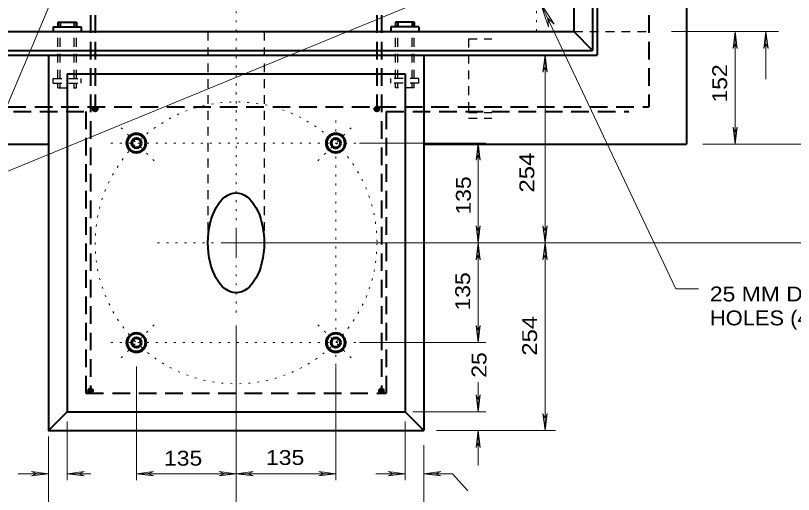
# Model space of a CAD drawing. Extents: x 312583 to 312854, y 144419 to 144597.
# Drawn here: x 312651.47 to 312691.2, y 144522.33 to 144546.77 of the extents above; entities that cross this region are included whole.
import ezdxf

# ---------------------------------------------------------------- set-up
doc = ezdxf.new("R2010")
doc.units = 0
doc.header["$LTSCALE"] = 0.3
for name, pattern in [('DOTTED', [1.5, 0.3, -1.2]), ('MEDIUM_DASHED', [4.5, 3, -1.5]), ('SHORT_DASHED', [2.7, 1.5, -1.2])]:
    doc.linetypes.add(name, pattern=pattern)
doc.layers.add('1', color=7, linetype='Continuous', lineweight=25)
doc.layers.add('2', color=7, linetype='Continuous', lineweight=13)

msp = doc.modelspace()

# ---------------------------------------------------------------- linework, layer by layer
at = {"layer": '1', "lineweight": 40}
for p, q in [((312685.7337, 144568.9533), (312685.7337, 144540.2033)), ((312679.9837, 144554.54), (312679.9837, 144545.9533)), ((312653.6257, 144546.4363), (312654.584, 144546.4363)), ((312653.6257, 144546.4363), (312653.6257, 144546.191)), ((312653.7484, 144546.4363), (312653.7484, 144546.191)), ((312654.469, 144546.4363), (312654.469, 144546.191)), ((312654.584, 144546.4363), (312654.584, 144546.191)), ((312671.834, 144546.4363), (312670.8757, 144546.4363)), ((312670.8757, 144546.4363), (312670.8757, 144546.191)), ((312670.9984, 144546.4363), (312670.9984, 144546.191)), ((312671.719, 144546.4363), (312671.719, 144546.191)), ((312671.834, 144546.4363), (312671.834, 144546.191)), ((312653.388, 144546.191), (312654.8217, 144546.191)), ((312653.388, 144546.191), (312653.388, 144545.9533)), ((312654.8217, 144546.191), (312654.8217, 144545.9533)), ((312672.0717, 144546.191), (312670.638, 144546.191)), ((312670.638, 144546.191), (312670.638, 144545.9533)), ((312672.0717, 144546.191), (312672.0717, 144545.9533)), ((312679.9837, 144545.9533), (312680.942, 144544.995)), ((312644.28, 144544.7573), (312681.1797, 144544.7573)), ((312644.5254, 144544.995), (312680.942, 144544.995)), ((312672.317, 144544.7573), (312672.317, 144525.5906)), ((312654.1087, 144543.799), (312654.1087, 144526.549)), ((312654.1087, 144543.799), (312671.3587, 144543.799)), ((312671.3587, 144543.799), (312671.3587, 144526.549)), ((312639.7337, 144540.2033), (312653.1504, 144540.2033)), ((312672.317, 144540.2033), (312685.7337, 144540.2033)), ((312654.1087, 144526.549), (312653.1504, 144525.5906)), ((312654.1087, 144526.549), (312671.3587, 144526.549)), ((312671.3587, 144526.549), (312672.317, 144525.5906))]:
    msp.add_line(p, q, dxfattribs=at)
at = {"layer": '1', "linetype": 'MEDIUM_DASHED', "lineweight": 40}
for p, q in [((312655.3047, 144567.0366), (312655.3047, 144527.6223)), ((312655.5424, 144567.0366), (312655.5424, 144542.12)), ((312669.9174, 144567.0366), (312669.9174, 144542.12)), ((312670.155, 144567.0366), (312670.155, 144527.6223)), ((312641.6504, 144542.12), (312683.817, 144542.12)), ((312643.2604, 144541.8823), (312655.067, 144541.8823)), ((312670.4004, 144541.8823), (312670.4004, 144527.5073)), ((312670.4004, 144541.8823), (312682.7974, 144541.8823))]:
    msp.add_line(p, q, dxfattribs=at)
at = {"layer": '1', "linetype": 'SHORT_DASHED'}
for p, q in [((312653.6257, 144543.5613), (312653.6257, 144545.9533)), ((312653.7484, 144543.5613), (312653.7484, 144545.9533)), ((312654.469, 144543.5613), (312654.469, 144545.9533)), ((312654.584, 144543.5613), (312654.584, 144545.9533)), ((312661.2924, 144545.9533), (312661.2924, 144535.174)), ((312664.1674, 144545.9533), (312664.1674, 144535.174)), ((312670.8757, 144543.5613), (312670.8757, 144545.9533)), ((312670.9984, 144543.5613), (312670.9984, 144545.9533)), ((312671.719, 144543.5613), (312671.719, 144545.9533)), ((312671.834, 144543.5613), (312671.834, 144545.9533)), ((312679.9837, 144545.9533), (312683.817, 144545.9533)), ((312674.594, 144545.593), (312675.79, 144545.593)), ((312674.594, 144545.593), (312674.594, 144541.5296)), ((312653.388, 144543.5613), (312654.8217, 144543.5613)), ((312653.388, 144543.316), (312653.388, 144543.5613)), ((312654.8217, 144543.316), (312654.8217, 144543.5613)), ((312672.0717, 144543.5613), (312670.638, 144543.5613)), ((312670.638, 144543.316), (312670.638, 144543.5613)), ((312672.0717, 144543.316), (312672.0717, 144543.5613)), ((312653.388, 144543.316), (312654.8217, 144543.316)), ((312653.6257, 144543.0783), (312653.6257, 144543.316)), ((312653.7484, 144543.0783), (312653.7484, 144543.316)), ((312654.469, 144543.0783), (312654.469, 144543.316)), ((312654.584, 144543.0783), (312654.584, 144543.316)), ((312672.0717, 144543.316), (312670.638, 144543.316)), ((312670.8757, 144543.0783), (312670.8757, 144543.316)), ((312670.9984, 144543.0783), (312670.9984, 144543.316)), ((312671.719, 144543.0783), (312671.719, 144543.316)), ((312671.834, 144543.0783), (312671.834, 144543.316)), ((312653.6257, 144543.0783), (312654.584, 144543.0783)), ((312671.834, 144543.0783), (312670.8757, 144543.0783)), ((312674.594, 144541.821), (312675.79, 144541.821)), ((312674.594, 144541.5296), (312675.79, 144541.5296))]:
    msp.add_line(p, q, dxfattribs=at)
at = {"layer": '1', "linetype": 'DOTTED', "lineweight": 13}
for p, q in [((312658.5554, 144539.3523), (312656.6694, 144541.2306)), ((312666.912, 144539.3523), (312668.7904, 144541.2306)), ((312667.8244, 144541.4223), (312667.8244, 144528.8643)), ((312656.332, 144540.2646), (312669.0357, 144540.2646)), ((312658.5554, 144530.9956), (312656.6694, 144529.1173)), ((312666.912, 144530.9956), (312668.7904, 144529.1173)), ((312656.332, 144530.0833), (312669.0357, 144530.0833))]:
    msp.add_line(p, q, dxfattribs=at)
at = {"layer": '1', "lineweight": 13}
msp.add_line((312673.789, 144523.3903), (312674.571, 144522.5163), dxfattribs=at)
at = {"layer": '1', "linetype": 'MEDIUM_DASHED', "lineweight": 40}
for points in [[(312641.842, 144567.0366), (312683.817, 144567.0366), (312683.817, 144542.12)], [(312655.067, 144541.8823), (312655.067, 144527.5073), (312670.4004, 144527.5073)]]:
    msp.add_lwpolyline(points, dxfattribs=at)
at = {"layer": '1', "lineweight": 40}
for points in [[(312644.28, 144564.3993), (312681.1797, 144564.3993), (312681.1797, 144544.7573)], [(312644.5254, 144564.1616), (312680.942, 144564.1616), (312680.942, 144544.995)], [(312645.4837, 144563.2033), (312645.4837, 144545.9533), (312679.9837, 144545.9533)], [(312653.1504, 144544.7573), (312653.1504, 144525.5906), (312672.317, 144525.5906)]]:
    msp.add_lwpolyline(points, dxfattribs=at)
at = {"layer": '1', "linetype": 'DOTTED', "lineweight": 13}
msp.add_circle((312662.7308, 144535.172), 7.2007, dxfattribs=at)
at = {"layer": '1', "lineweight": 40}
for centre, radius in [((312655.5433, 144542.0002), 0.1198), ((312655.5433, 144542.0002), 0.0838), ((312655.5433, 144542.0002), 0.0587), ((312669.9183, 144542.0002), 0.1198), ((312669.9183, 144542.0002), 0.0838), ((312669.9183, 144542.0002), 0.0587), ((312655.3037, 144527.6252), 0.1198), ((312655.3037, 144527.6252), 0.0838), ((312655.3037, 144527.6252), 0.0587), ((312670.1579, 144527.6252), 0.1198), ((312670.1579, 144527.6252), 0.0838), ((312670.1579, 144527.6252), 0.0587)]:
    msp.add_circle(centre, radius, dxfattribs=at)
at = {"layer": '1', "lineweight": 60}
for centre, radius in [((312657.6392, 144540.2637), 0.4792), ((312667.8224, 144540.2637), 0.4792), ((312657.6392, 144540.2637), 0.2396), ((312667.8224, 144540.2637), 0.2396), ((312657.6392, 144530.0804), 0.4792), ((312667.8224, 144530.0804), 0.4792), ((312657.6392, 144530.0804), 0.2396), ((312667.8224, 144530.0804), 0.2396)]:
    msp.add_circle(centre, radius, dxfattribs=at)
at = {"layer": '1', "lineweight": 40}
msp.add_ellipse((312662.7308, 144535.1725), major_axis=(0, -2.5458), ratio=0.564653, dxfattribs=at)
at = {"layer": '2'}
for p, q in [((312659.9354, 144563.2033), (312649.317, 144538.118)), ((312649.317, 144538.118), (312679.9837, 144550.7143)), ((312678.2664, 144547.4406), (312685.1894, 144532.8203)), ((312678.2664, 144547.4406), (312678.6804, 144546.191)), ((312678.2664, 144547.4406), (312678.9717, 144546.329)), ((312678.6804, 144546.191), (312678.6497, 144546.6356)), ((312678.9717, 144546.329), (312678.6497, 144546.6356)), ((312684.967, 144545.9533), (312690.4331, 144545.9533)), ((312688.2189, 144545.9533), (312688.1116, 144545.087)), ((312688.2189, 144540.2033), (312688.2189, 144545.9533)), ((312688.2189, 144545.9533), (312688.3262, 144545.087)), ((312689.793, 144545.9533), (312689.6856, 144545.087)), ((312689.793, 144543.523), (312689.793, 144545.9533)), ((312689.793, 144545.9533), (312689.9003, 144545.087)), ((312688.1116, 144545.087), (312688.2189, 144545.363)), ((312688.3262, 144545.087), (312688.2189, 144545.363)), ((312689.6856, 144545.087), (312689.793, 144545.363)), ((312689.9003, 144545.087), (312689.793, 144545.363)), ((312678.5117, 144544.7573), (312678.4044, 144543.891)), ((312678.5117, 144544.7573), (312678.619, 144543.891)), ((312678.4044, 144543.891), (312678.5117, 144544.167)), ((312678.619, 144543.891), (312678.5117, 144544.167)), ((312688.1116, 144541.0696), (312688.2189, 144540.7936)), ((312688.2189, 144540.2033), (312688.1116, 144541.0696)), ((312688.3262, 144541.0696), (312688.2189, 144540.7936)), ((312688.2189, 144540.2033), (312688.3262, 144541.0696)), ((312669.0357, 144540.2646), (312675.491, 144540.2646)), ((312675.0924, 144540.2646), (312674.985, 144539.3983)), ((312675.0924, 144540.2646), (312675.1997, 144539.3983)), ((312686.5694, 144540.2033), (312694.742, 144540.2033)), ((312674.985, 144539.3983), (312675.0924, 144539.6743)), ((312675.1997, 144539.3983), (312675.0924, 144539.6743)), ((312674.985, 144536.0403), (312675.0924, 144535.7643)), ((312675.0924, 144535.174), (312674.985, 144536.0403)), ((312675.1997, 144536.0403), (312675.0924, 144535.7643)), ((312675.0924, 144535.174), (312675.1997, 144536.0403)), ((312678.4044, 144536.0403), (312678.5117, 144535.7643)), ((312678.5117, 144535.174), (312678.4044, 144536.0403)), ((312678.619, 144536.0403), (312678.5117, 144535.7643)), ((312678.5117, 144535.174), (312678.619, 144536.0403)), ((312662.7337, 144535.174), (312662.7337, 144535.9406)), ((312662.7337, 144535.174), (312661.967, 144535.174)), ((312662.7337, 144535.174), (312693.5692, 144535.174)), ((312662.7337, 144535.174), (312663.5004, 144535.174)), ((312662.7337, 144535.174), (312662.7337, 144534.4073)), ((312675.0924, 144535.174), (312674.985, 144534.3076)), ((312675.0924, 144535.174), (312675.1997, 144534.3076)), ((312678.5117, 144535.174), (312678.4044, 144534.3076)), ((312678.5117, 144535.174), (312678.619, 144534.3076)), ((312674.985, 144534.3076), (312675.0924, 144534.5836)), ((312675.1997, 144534.3076), (312675.0924, 144534.5836)), ((312678.4044, 144534.3076), (312678.5117, 144534.5836)), ((312678.619, 144534.3076), (312678.5117, 144534.5836)), ((312686.3547, 144532.8203), (312685.1894, 144532.8203)), ((312662.7337, 144530.9496), (312662.7337, 144520.3543)), ((312674.985, 144530.9496), (312675.0924, 144530.6736)), ((312675.0924, 144530.0833), (312674.985, 144530.9496)), ((312675.1997, 144530.9496), (312675.0924, 144530.6736)), ((312675.0924, 144530.0833), (312675.1997, 144530.9496)), ((312669.0357, 144530.0833), (312675.491, 144530.0833)), ((312657.643, 144528.8643), (312657.643, 144523.053)), ((312667.8244, 144528.8643), (312667.8244, 144523.053)), ((312675.0924, 144526.549), (312675.0924, 144528.0593)), ((312674.985, 144527.4153), (312675.0924, 144527.1393)), ((312675.0924, 144526.549), (312674.985, 144527.4153)), ((312675.1997, 144527.4153), (312675.0924, 144527.1393)), ((312675.0924, 144526.549), (312675.1997, 144527.4153)), ((312671.7574, 144526.549), (312675.491, 144526.549)), ((312678.4044, 144526.457), (312678.5117, 144526.181)), ((312678.5117, 144525.5906), (312678.4044, 144526.457)), ((312678.619, 144526.457), (312678.5117, 144526.181)), ((312678.5117, 144525.5906), (312678.619, 144526.457)), ((312654.1087, 144526.0506), (312654.1087, 144523.053)), ((312671.3587, 144526.0506), (312671.3587, 144523.053)), ((312653.1504, 144525.284), (312653.1504, 144517.809)), ((312672.9687, 144525.5906), (312679.0407, 144525.5906)), ((312675.0924, 144525.5906), (312674.985, 144524.7243)), ((312675.0924, 144523.8043), (312675.0924, 144525.5906)), ((312675.0924, 144525.5906), (312675.1997, 144524.7243)), ((312672.317, 144524.847), (312672.317, 144517.809)), ((312674.985, 144524.7243), (312675.0924, 144525.0003)), ((312675.1997, 144524.7243), (312675.0924, 144525.0003)), ((312651.6017, 144523.3903), (312653.1504, 144523.3903)), ((312652.284, 144523.4976), (312652.56, 144523.3903)), ((312653.1504, 144523.3903), (312652.284, 144523.4976)), ((312652.284, 144523.283), (312652.56, 144523.3903)), ((312653.1504, 144523.3903), (312652.284, 144523.283)), ((312654.1087, 144523.3903), (312654.975, 144523.4976)), ((312654.1087, 144523.3903), (312655.32, 144523.3903)), ((312654.1087, 144523.3903), (312654.975, 144523.283)), ((312654.975, 144523.4976), (312654.699, 144523.3903)), ((312654.975, 144523.283), (312654.699, 144523.3903)), ((312657.643, 144523.3903), (312658.5094, 144523.4976)), ((312657.643, 144523.3903), (312662.7337, 144523.3903)), ((312657.643, 144523.3903), (312658.5094, 144523.283)), ((312658.5094, 144523.4976), (312658.2334, 144523.3903)), ((312658.5094, 144523.283), (312658.2334, 144523.3903)), ((312661.8674, 144523.4976), (312662.1434, 144523.3903)), ((312662.7337, 144523.3903), (312661.8674, 144523.4976)), ((312661.8674, 144523.283), (312662.1434, 144523.3903)), ((312662.7337, 144523.3903), (312661.8674, 144523.283)), ((312662.7337, 144523.3903), (312663.6, 144523.4976)), ((312662.7337, 144523.3903), (312667.8244, 144523.3903)), ((312662.7337, 144523.3903), (312663.6, 144523.283)), ((312663.6, 144523.4976), (312663.324, 144523.3903)), ((312663.6, 144523.283), (312663.324, 144523.3903)), ((312666.958, 144523.4976), (312667.234, 144523.3903)), ((312667.8244, 144523.3903), (312666.958, 144523.4976)), ((312666.958, 144523.283), (312667.234, 144523.3903)), ((312667.8244, 144523.3903), (312666.958, 144523.283)), ((312669.8637, 144523.3903), (312671.3587, 144523.3903)), ((312670.4924, 144523.4976), (312670.7684, 144523.3903)), ((312671.3587, 144523.3903), (312670.4924, 144523.4976)), ((312670.4924, 144523.283), (312670.7684, 144523.3903)), ((312671.3587, 144523.3903), (312670.4924, 144523.283)), ((312672.317, 144523.3903), (312673.1834, 144523.4976)), ((312672.317, 144523.3903), (312673.789, 144523.3903)), ((312672.317, 144523.3903), (312673.1834, 144523.283)), ((312673.1834, 144523.4976), (312672.9074, 144523.3903)), ((312673.1834, 144523.283), (312672.9074, 144523.3903))]:
    msp.add_line(p, q, dxfattribs=at)
at = {"layer": '2', "linetype": 'DOTTED'}
for p, q in [((312662.7337, 144553.4283), (312662.7337, 144541.4453)), ((312678.067, 144547.4636), (312678.067, 144545.8996)), ((312662.7337, 144536.324), (312662.7337, 144543.9906)), ((312661.5837, 144535.174), (312658.5017, 144535.174)), ((312663.8837, 144535.174), (312666.8124, 144535.174)), ((312662.7337, 144534.024), (312662.7337, 144531.4096))]:
    msp.add_line(p, q, dxfattribs=at)
at = {"layer": '2'}
for points in [[(312678.5117, 144525.5906), (312678.5117, 144535.174), (312678.5117, 144544.7573)], [(312675.0924, 144530.0833), (312675.0924, 144535.174), (312675.0924, 144540.2646)]]:
    msp.add_lwpolyline(points, dxfattribs=at)

# ---------------------------------------------------------------- texts
for s, width, p in [('152 ', 1.15, (312687.8102, 144542.3346)), ('254 ', 1.2, (312677.9613, 144537.7409)), ('135 ', 1.15, (312674.7191, 144536.6173)), ('135 ', 1.15, (312674.6838, 144531.7191)), ('254 ', 1.2, (312678.103, 144529.4123)), ('25 ', 1.15, (312675.5184, 144528.2874))]:
    msp.add_text(s, height=0.76, rotation=90, dxfattribs=dict(at, width=width)).set_placement(p)
for s, width, p in [('25 MM DIA. GROUND ROD', 1.15, (312686.9276, 144532.1812)), ('HOLES (4)', 1.1, (312686.9276, 144530.9612)), ('135 ', 1.15, (312659.0526, 144523.7995)), ('135 ', 1.15, (312664.2621, 144523.835))]:
    msp.add_text(s, height=0.76, dxfattribs=dict(at, width=width)).set_placement(p)

doc.saveas('drawing.dxf')
